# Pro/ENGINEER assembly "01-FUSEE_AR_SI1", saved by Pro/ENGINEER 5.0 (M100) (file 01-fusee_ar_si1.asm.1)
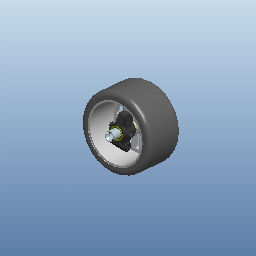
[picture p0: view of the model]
Units: millimeter Newton Second (mmNs); MM, TONNE, HOURS

Other components: E_PORTE-FUSEE, E_ROUE

Other named items: A-DROITE, A-DESSUS, A-FACE, A-R0, C_ROUE, S1

Family table entries: GENERIC, E_PORTE-FUSEE#AF0, E_PORTE-FUSEE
